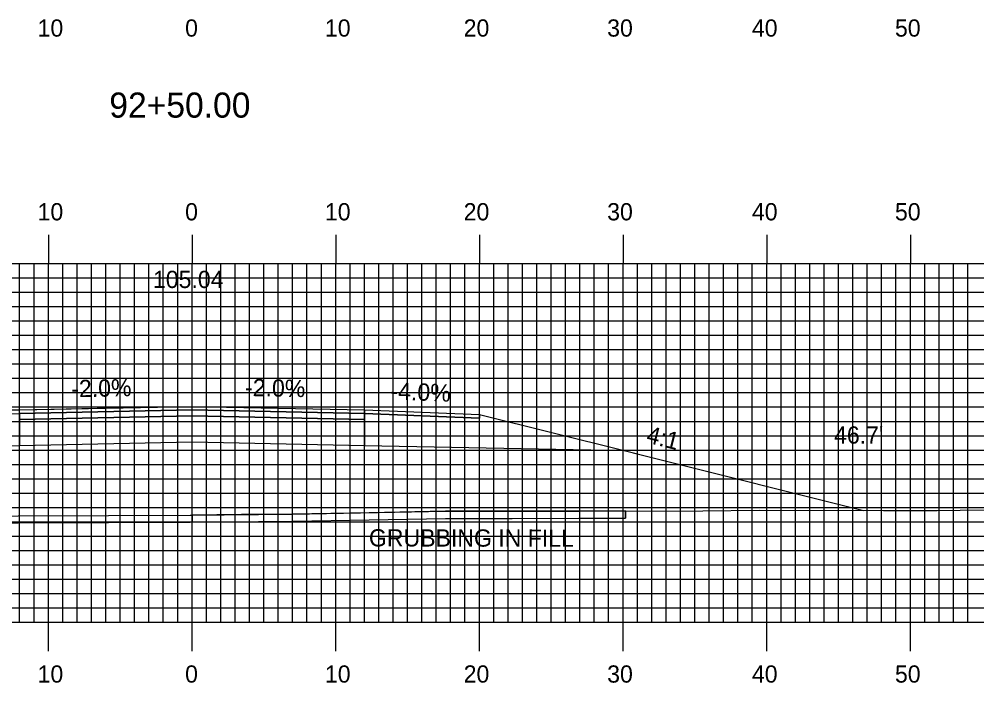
# Model space of a CAD drawing. Extents: x 1764939 to 1765282, y 442591 to 442811.
# Drawn here: x 1765092.8 to 1765159.5, y 442644.4 to 442690.7 of the extents above; entities that cross this region are included whole.
import ezdxf

# ---------------------------------------------------------------- set-up
doc = ezdxf.new("R2010")
doc.units = 0
for name, color, linetype in [('ANNOTATION', 7, 'Continuous'), ('D_Roadway_Centerline', 7, 'Continuous'), ('D_Roadway_Centerline_Text', 7, 'Continuous'), ('D_Roadway_Edge_Shoulder', 7, 'Continuous'), ('D_Roadway_Edge_TW', 7, 'Continuous'), ('D_Roadway_Pavement', 7, 'Continuous'), ('D_Roadway_SlopeLines', 7, 'Continuous'), ('D_Roadway_SubGrade', 7, 'Continuous'), ('D_Text_Standard', 7, 'Continuous'), ('GRUBBING IN FILL', 7, 'Continuous'), ('H_V ANNOTATION', 7, 'Continuous'), ('MAJOR', 7, 'Continuous'), ('MINOR', 7, 'Continuous'), ('S_Roadway_Centerline', 7, 'Continuous')]:
    doc.layers.add(name, color=color, linetype=linetype)

msp = doc.modelspace()

# ---------------------------------------------------------------- linework, layer by layer
at = {"layer": 'D_Roadway_Centerline'}
msp.add_lwpolyline([(1765054.903, 442655.657), (1765074.679, 442660.601), (1765074.684, 442660.602), (1765074.687, 442660.603), (1765084.858, 442663.146), (1765092.858, 442663.466), (1765092.863, 442663.466), (1765098.249, 442663.574), (1765104.852, 442663.706), (1765104.858, 442663.706), (1765116.852, 442663.466), (1765116.858, 442663.466), (1765116.862, 442663.466), (1765124.858, 442663.146), (1765124.86, 442663.146), (1765135.032, 442660.602), (1765136.029, 442660.353), (1765136.858, 442660.146), (1765151.587, 442656.463), (1765151.59, 442656.462)], dxfattribs=at)
at = {"layer": 'D_Roadway_Edge_Shoulder'}
for points in [[(1765092.858, 442663.466), (1765084.858, 442663.146), (1765084.858, 442662.896), (1765092.858, 442663.216)], [(1765116.858, 442663.466), (1765124.858, 442663.146), (1765124.858, 442662.896), (1765116.858, 442663.216)]]:
    msp.add_lwpolyline(points, close=True, dxfattribs=at)
at = {"layer": 'D_Roadway_Edge_TW'}
for points in [[(1765092.858, 442663.216), (1765092.858, 442663.466), (1765104.858, 442663.706), (1765116.858, 442663.466), (1765116.858, 442663.216), (1765104.858, 442663.456)], [(1765116.858, 442663.466), (1765116.858, 442663.466), (1765116.858, 442663.216), (1765116.858, 442663.216)]]:
    msp.add_lwpolyline(points, close=True, dxfattribs=at)
at = {"layer": 'D_Roadway_Pavement'}
for points in [[(1765092.858, 442662.799), (1765092.858, 442663.216), (1765104.858, 442663.456), (1765116.858, 442663.216), (1765116.858, 442662.799), (1765104.858, 442663.039)], [(1765116.858, 442663.216), (1765116.858, 442663.216), (1765116.858, 442662.799), (1765116.858, 442662.799)]]:
    msp.add_lwpolyline(points, close=True, dxfattribs=at)
msp.add_lwpolyline([(1765116.858, 442663.216), (1765116.858, 442662.799)], dxfattribs=at)
msp.add_lwpolyline([(1765116.858, 442663.216), (1765116.858, 442662.799)], dxfattribs=at)
msp.add_lwpolyline([(1765116.858, 442663.216), (1765116.858, 442662.799)], dxfattribs=at)
at = {"layer": 'D_Roadway_SlopeLines'}
msp.add_lwpolyline([(1765124.858, 442663.146), (1765135.032, 442660.602), (1765136.858, 442660.146), (1765151.59, 442656.462)], dxfattribs=at)
at = {"layer": 'D_Roadway_SubGrade'}
for points in [[(1765084.858, 442662.896), (1765092.858, 442663.216), (1765092.858, 442662.799), (1765092.858, 442660.966), (1765074.684, 442660.602), (1765084.858, 442663.146)], [(1765116.858, 442662.799), (1765116.858, 442663.216), (1765124.858, 442662.896), (1765124.858, 442663.146), (1765135.032, 442660.602), (1765116.858, 442660.966)], [(1765092.858, 442660.966), (1765092.858, 442662.799), (1765104.858, 442663.039), (1765116.858, 442662.799), (1765116.858, 442660.966), (1765104.858, 442661.206)], [(1765116.858, 442662.799), (1765116.858, 442662.799), (1765116.858, 442660.966), (1765116.858, 442660.966)]]:
    msp.add_lwpolyline(points, close=True, dxfattribs=at)
at = {"layer": 'GRUBBING IN FILL'}
msp.add_line((1765135.032, 442656.421), (1765135.032, 442655.921), dxfattribs=at)
for points in [[(1765074.684, 442655.454), (1765074.684, 442655.954), (1765080.138, 442656.008), (1765086.459, 442656.071), (1765092.748, 442656.091), (1765099.037, 442656.11), (1765104.858, 442656.135), (1765104.858, 442655.635), (1765101.883, 442655.622), (1765099.038, 442655.61), (1765092.751, 442655.591), (1765086.463, 442655.571), (1765080.573, 442655.512)], [(1765074.684, 442655.454), (1765074.684, 442655.954), (1765080.138, 442656.008), (1765086.459, 442656.071), (1765092.748, 442656.091), (1765099.037, 442656.11), (1765104.858, 442656.135), (1765104.858, 442655.635), (1765101.883, 442655.622), (1765099.038, 442655.61), (1765092.751, 442655.591), (1765086.463, 442655.571), (1765080.573, 442655.512)], [(1765135.032, 442655.921), (1765135.032, 442656.421), (1765131.775, 442656.413), (1765127.137, 442656.407), (1765122.498, 442656.402), (1765117.177, 442656.303), (1765111.857, 442656.203), (1765108.29, 442656.168), (1765104.858, 442656.135), (1765104.858, 442655.635), (1765108.296, 442655.668), (1765111.864, 442655.703), (1765117.183, 442655.803), (1765122.503, 442655.902), (1765127.139, 442655.907), (1765131.776, 442655.913)], [(1765135.032, 442655.921), (1765135.032, 442656.421), (1765131.775, 442656.413), (1765127.137, 442656.407), (1765122.498, 442656.402), (1765117.177, 442656.303), (1765111.857, 442656.203), (1765108.29, 442656.168), (1765104.858, 442656.135), (1765104.858, 442655.635), (1765108.296, 442655.668), (1765111.864, 442655.703), (1765117.183, 442655.803), (1765122.503, 442655.902), (1765127.139, 442655.907), (1765131.776, 442655.913)]]:
    msp.add_lwpolyline(points, close=True, dxfattribs=at)
msp.add_lwpolyline([(1765074.684, 442655.454), (1765086.463, 442655.571), (1765099.038, 442655.61), (1765104.728, 442655.633), (1765111.864, 442655.703), (1765122.503, 442655.902), (1765131.776, 442655.913), (1765135.032, 442655.921)], dxfattribs=at)
at = {"layer": 'MAJOR'}
for p, q in [((1765094.858, 442675.669), (1765094.858, 442673.665)), ((1765104.858, 442675.669), (1765104.858, 442673.665)), ((1765114.858, 442675.669), (1765114.858, 442673.665)), ((1765124.858, 442675.669), (1765124.858, 442673.665)), ((1765134.858, 442675.669), (1765134.858, 442673.665)), ((1765144.858, 442675.669), (1765144.858, 442673.665)), ((1765154.858, 442675.669), (1765154.858, 442673.665)), ((1764964.858, 442673.665), (1765244.858, 442673.665)), ((1764964.858, 442673.665), (1765244.858, 442673.665)), ((1765094.858, 442648.665), (1765094.858, 442673.665)), ((1765104.858, 442648.665), (1765104.858, 442673.665)), ((1765114.858, 442648.665), (1765114.858, 442673.665)), ((1765124.858, 442648.665), (1765124.858, 442673.665)), ((1765134.858, 442648.665), (1765134.858, 442673.665)), ((1765144.858, 442648.665), (1765144.858, 442673.665)), ((1765154.858, 442648.665), (1765154.858, 442673.665)), ((1764964.858, 442668.665), (1765244.858, 442668.665)), ((1764964.858, 442663.665), (1765244.858, 442663.665)), ((1764964.858, 442658.665), (1765244.858, 442658.665)), ((1764964.858, 442653.665), (1765244.858, 442653.665)), ((1764964.858, 442648.665), (1765244.858, 442648.665)), ((1764964.858, 442648.665), (1765244.858, 442648.665)), ((1765094.858, 442646.661), (1765094.858, 442648.665)), ((1765104.858, 442646.661), (1765104.858, 442648.665)), ((1765114.858, 442646.661), (1765114.858, 442648.665)), ((1765124.858, 442646.661), (1765124.858, 442648.665)), ((1765134.858, 442646.661), (1765134.858, 442648.665)), ((1765144.858, 442646.661), (1765144.858, 442648.665)), ((1765154.858, 442646.661), (1765154.858, 442648.665))]:
    msp.add_line(p, q, dxfattribs=at)
at = {"layer": 'MINOR'}
for p, q in [((1765092.858, 442648.665), (1765092.858, 442673.665)), ((1765093.858, 442648.665), (1765093.858, 442673.665)), ((1765095.858, 442648.665), (1765095.858, 442673.665)), ((1765096.858, 442648.665), (1765096.858, 442673.665)), ((1765097.858, 442648.665), (1765097.858, 442673.665)), ((1765098.858, 442648.665), (1765098.858, 442673.665)), ((1765099.858, 442648.665), (1765099.858, 442673.665)), ((1765100.858, 442648.665), (1765100.858, 442673.665)), ((1765101.858, 442648.665), (1765101.858, 442673.665)), ((1765102.858, 442648.665), (1765102.858, 442673.665)), ((1765103.858, 442648.665), (1765103.858, 442673.665)), ((1765105.858, 442648.665), (1765105.858, 442673.665)), ((1765106.858, 442648.665), (1765106.858, 442673.665)), ((1765107.858, 442648.665), (1765107.858, 442673.665)), ((1765108.858, 442648.665), (1765108.858, 442673.665)), ((1765109.858, 442648.665), (1765109.858, 442673.665)), ((1765110.858, 442648.665), (1765110.858, 442673.665)), ((1765111.858, 442648.665), (1765111.858, 442673.665)), ((1765112.858, 442648.665), (1765112.858, 442673.665)), ((1765113.858, 442648.665), (1765113.858, 442673.665)), ((1765115.858, 442648.665), (1765115.858, 442673.665)), ((1765116.858, 442648.665), (1765116.858, 442673.665)), ((1765117.858, 442648.665), (1765117.858, 442673.665)), ((1765118.858, 442648.665), (1765118.858, 442673.665)), ((1765119.858, 442648.665), (1765119.858, 442673.665)), ((1765120.858, 442648.665), (1765120.858, 442673.665)), ((1765121.858, 442648.665), (1765121.858, 442673.665)), ((1765122.858, 442648.665), (1765122.858, 442673.665)), ((1765123.858, 442648.665), (1765123.858, 442673.665)), ((1765125.858, 442648.665), (1765125.858, 442673.665)), ((1765126.858, 442648.665), (1765126.858, 442673.665)), ((1765127.858, 442648.665), (1765127.858, 442673.665)), ((1765128.858, 442648.665), (1765128.858, 442673.665)), ((1765129.858, 442648.665), (1765129.858, 442673.665)), ((1765130.858, 442648.665), (1765130.858, 442673.665)), ((1765131.858, 442648.665), (1765131.858, 442673.665)), ((1765132.858, 442648.665), (1765132.858, 442673.665)), ((1765133.858, 442648.665), (1765133.858, 442673.665)), ((1765135.858, 442648.665), (1765135.858, 442673.665)), ((1765136.858, 442648.665), (1765136.858, 442673.665)), ((1765137.858, 442648.665), (1765137.858, 442673.665)), ((1765138.858, 442648.665), (1765138.858, 442673.665)), ((1765139.858, 442648.665), (1765139.858, 442673.665)), ((1765140.858, 442648.665), (1765140.858, 442673.665)), ((1765141.858, 442648.665), (1765141.858, 442673.665)), ((1765142.858, 442648.665), (1765142.858, 442673.665)), ((1765143.858, 442648.665), (1765143.858, 442673.665)), ((1765145.858, 442648.665), (1765145.858, 442673.665)), ((1765146.858, 442648.665), (1765146.858, 442673.665)), ((1765147.858, 442648.665), (1765147.858, 442673.665)), ((1765148.858, 442648.665), (1765148.858, 442673.665)), ((1765149.858, 442648.665), (1765149.858, 442673.665)), ((1765150.858, 442648.665), (1765150.858, 442673.665)), ((1765151.858, 442648.665), (1765151.858, 442673.665)), ((1765152.858, 442648.665), (1765152.858, 442673.665)), ((1765153.858, 442648.665), (1765153.858, 442673.665)), ((1765155.858, 442648.665), (1765155.858, 442673.665)), ((1765156.858, 442648.665), (1765156.858, 442673.665)), ((1765157.858, 442648.665), (1765157.858, 442673.665)), ((1765158.858, 442648.665), (1765158.858, 442673.665)), ((1764964.858, 442672.665), (1765244.858, 442672.665)), ((1764964.858, 442671.665), (1765244.858, 442671.665)), ((1764964.858, 442670.665), (1765244.858, 442670.665)), ((1764964.858, 442669.665), (1765244.858, 442669.665)), ((1764964.858, 442667.665), (1765244.858, 442667.665)), ((1764964.858, 442666.665), (1765244.858, 442666.665)), ((1764964.858, 442665.665), (1765244.858, 442665.665)), ((1764964.858, 442664.665), (1765244.858, 442664.665)), ((1764964.858, 442662.665), (1765244.858, 442662.665)), ((1764964.858, 442661.665), (1765244.858, 442661.665)), ((1764964.858, 442660.665), (1765244.858, 442660.665)), ((1764964.858, 442659.665), (1765244.858, 442659.665)), ((1764964.858, 442657.665), (1765244.858, 442657.665)), ((1764964.858, 442656.665), (1765244.858, 442656.665)), ((1764964.858, 442655.665), (1765244.858, 442655.665)), ((1764964.858, 442654.665), (1765244.858, 442654.665)), ((1764964.858, 442652.665), (1765244.858, 442652.665)), ((1764964.858, 442651.665), (1765244.858, 442651.665)), ((1764964.858, 442650.665), (1765244.858, 442650.665)), ((1764964.858, 442649.665), (1765244.858, 442649.665))]:
    msp.add_line(p, q, dxfattribs=at)
at = {"layer": 'S_Roadway_Centerline'}
msp.add_lwpolyline([(1765086.459, 442656.071), (1765099.037, 442656.11), (1765104.724, 442656.133), (1765111.857, 442656.203), (1765122.498, 442656.402), (1765131.775, 442656.413), (1765140.424, 442656.434), (1765144.33, 442656.482), (1765152.987, 442656.459), (1765156.722, 442656.462), (1765158.336, 442656.474), (1765169.053, 442656.615)], dxfattribs=at)

# ---------------------------------------------------------------- texts
at = {"layer": 'ANNOTATION'}
for s, rotation, p in [('-2.0%', 1.14571, (1765096.463, 442664.339)), ('-2.0%', 358.85423, (1765108.541, 442664.433)), ('-4.0%', 357.70952, (1765118.652, 442664.196)), ('4:1', 345.96057, (1765136.421, 442661.201))]:
    msp.add_text(s, height=1.2, rotation=rotation, dxfattribs=at).set_placement(p)
at = {"layer": 'D_Roadway_Centerline'}
for s, p in [('C', (1765104.853, 442663.706)), ('L', (1765104.858, 442663.699))]:
    msp.add_text(s, height=0.0146, dxfattribs=at).set_placement(p)
at = {"layer": 'D_Roadway_Centerline_Text'}
msp.add_text('105.04', height=1.2, dxfattribs=at).set_placement((1765102.139, 442671.953))
at = {"layer": 'D_Text_Standard'}
msp.add_text("46.7'", height=1.2, dxfattribs=at).set_placement((1765149.549, 442661.115))
at = {"layer": 'GRUBBING IN FILL'}
msp.add_text('GRUBBING IN FILL', height=1.2, rotation=359.89036, dxfattribs=at).set_placement((1765117.17, 442653.953))
at = {"layer": 'H_V ANNOTATION'}
for s, height, p in [('10', 1.2, (1765094.109, 442689.465)), ('0', 1.2, (1765104.376, 442689.465)), ('10', 1.2, (1765114.109, 442689.465)), ('20', 1.2, (1765123.766, 442689.465)), ('30', 1.2, (1765133.755, 442689.465)), ('40', 1.2, (1765143.83, 442689.465)), ('50', 1.2, (1765153.787, 442689.465)), ('92+50.00', 1.75, (1765099.099, 442683.821)), ('10', 1.2, (1765094.109, 442676.665)), ('0', 1.2, (1765104.376, 442676.665)), ('10', 1.2, (1765114.109, 442676.665)), ('20', 1.2, (1765123.766, 442676.665)), ('30', 1.2, (1765133.755, 442676.665)), ('40', 1.2, (1765143.83, 442676.665)), ('50', 1.2, (1765153.787, 442676.665)), ('10', 1.2, (1765094.109, 442644.465)), ('0', 1.2, (1765104.376, 442644.465)), ('10', 1.2, (1765114.109, 442644.465)), ('20', 1.2, (1765123.766, 442644.465)), ('30', 1.2, (1765133.755, 442644.465)), ('40', 1.2, (1765143.83, 442644.465)), ('50', 1.2, (1765153.787, 442644.465))]:
    msp.add_text(s, height=height, dxfattribs=at).set_placement(p)

doc.saveas('drawing.dxf')
